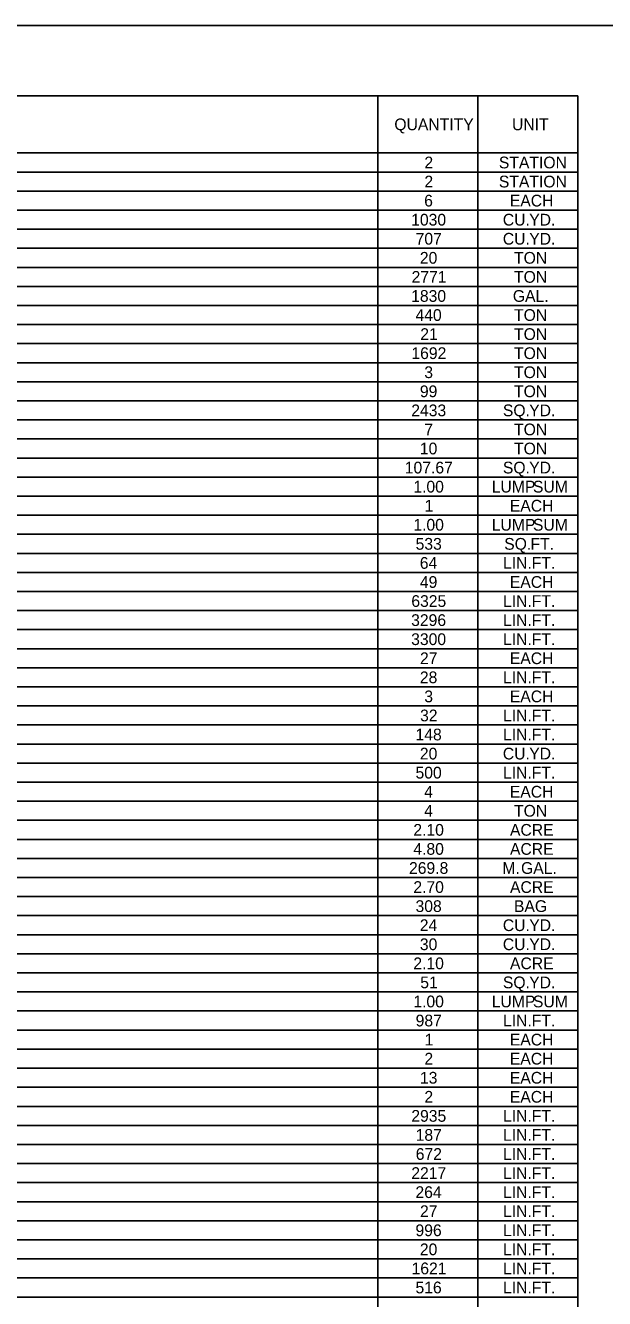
# Model space of a CAD drawing. Extents: x 3289 to 10164, y -1238 to -188.
# Drawn here: x 9306 to 9602, y -839 to -188 of the extents above; entities that cross this region are included whole.
import ezdxf

# ---------------------------------------------------------------- set-up
doc = ezdxf.new("R2010")
doc.units = 0
for name, color, linetype in [('Default', 7, 'Continuous'), ('DSN_DRFT_Named-Boundary', 7, 'Continuous'), ('DSN_QNTY_Annotation', 7, 'Continuous')]:
    doc.layers.add(name, color=color, linetype=linetype)

msp = doc.modelspace()

# ---------------------------------------------------------------- linework, layer by layer
at = {"layer": 'DSN_DRFT_Named-Boundary'}
msp.add_lwpolyline([(8538.57, -1237.74), (10163.57, -1237.74), (10163.57, -187.74), (8538.57, -187.74)], close=True, dxfattribs=at)
at = {"layer": 'DSN_QNTY_Annotation'}
for p, q in [((8900.84, -223.68), (9588.8, -223.68)), ((9486.62, -223.68), (9588.8, -223.68)), ((9486.62, -1023.18), (9486.62, -223.68)), ((9537.71, -1023.18), (9537.71, -223.68)), ((9537.71, -1023.18), (9537.71, -223.68)), ((9588.8, -1023.18), (9588.8, -223.68)), ((8900.84, -252.93), (9588.8, -252.93)), ((9486.62, -837.93), (9486.62, -252.93)), ((8900.84, -262.68), (9588.8, -262.68)), ((8900.84, -272.43), (9588.8, -272.43)), ((8900.84, -282.18), (9588.8, -282.18)), ((8900.84, -291.93), (9588.8, -291.93)), ((8900.84, -301.68), (9588.8, -301.68)), ((8900.84, -311.43), (9588.8, -311.43)), ((8900.84, -321.18), (9588.8, -321.18)), ((8900.84, -330.93), (9588.8, -330.93)), ((8900.84, -340.68), (9588.8, -340.68)), ((8900.84, -350.43), (9588.8, -350.43)), ((8900.84, -360.18), (9588.8, -360.18)), ((8900.84, -369.93), (9588.8, -369.93)), ((8900.84, -379.68), (9588.8, -379.68)), ((8900.84, -389.43), (9588.8, -389.43)), ((8900.84, -399.18), (9588.8, -399.18)), ((8900.84, -408.93), (9588.8, -408.93)), ((8900.84, -418.68), (9588.8, -418.68)), ((8900.84, -428.43), (9588.8, -428.43)), ((8900.84, -438.18), (9588.8, -438.18)), ((8900.84, -447.93), (9588.8, -447.93)), ((8900.84, -457.68), (9588.8, -457.68)), ((8900.84, -467.43), (9588.8, -467.43)), ((8900.84, -477.18), (9588.8, -477.18)), ((8900.84, -486.93), (9588.8, -486.93)), ((8900.84, -496.68), (9588.8, -496.68)), ((8900.84, -506.43), (9588.8, -506.43)), ((8900.84, -516.18), (9588.8, -516.18)), ((8900.84, -525.93), (9588.8, -525.93)), ((8900.84, -535.68), (9588.8, -535.68)), ((8900.84, -545.43), (9588.8, -545.43)), ((8900.84, -555.18), (9588.8, -555.18)), ((8900.84, -564.93), (9588.8, -564.93)), ((8900.84, -574.68), (9588.8, -574.68)), ((8900.84, -584.43), (9588.8, -584.43)), ((8900.84, -594.18), (9588.8, -594.18)), ((8900.84, -603.93), (9588.8, -603.93)), ((8900.84, -613.68), (9588.8, -613.68)), ((8900.84, -623.43), (9588.8, -623.43)), ((8900.84, -633.18), (9588.8, -633.18)), ((8900.84, -642.93), (9588.8, -642.93)), ((8900.84, -652.68), (9588.8, -652.68)), ((8900.84, -662.43), (9588.8, -662.43)), ((8900.84, -672.18), (9588.8, -672.18)), ((8900.84, -681.93), (9588.8, -681.93)), ((8900.84, -691.68), (9588.8, -691.68)), ((8900.84, -701.43), (9588.8, -701.43)), ((8900.84, -711.18), (9588.8, -711.18)), ((8900.84, -720.93), (9588.8, -720.93)), ((8900.84, -730.68), (9588.8, -730.68)), ((8900.84, -740.43), (9588.8, -740.43)), ((8900.84, -750.18), (9588.8, -750.18)), ((8900.84, -759.93), (9588.8, -759.93)), ((8900.84, -769.68), (9588.8, -769.68)), ((8900.84, -779.43), (9588.8, -779.43)), ((8900.84, -789.18), (9588.8, -789.18)), ((8900.84, -798.93), (9588.8, -798.93)), ((8900.84, -808.68), (9588.8, -808.68)), ((8900.84, -818.43), (9588.8, -818.43)), ((8900.84, -828.18), (9588.8, -828.18)), ((8900.84, -837.93), (9588.8, -837.93))]:
    msp.add_line(p, q, dxfattribs=at)

# ---------------------------------------------------------------- texts
at = {"layer": 'Default'}
for s, p in [('QUANTITY', (9495, -241.31)), ('UNIT', (9555.16, -241.31)), ('2', (9510.38, -260.81)), ('STATION', (9548.43, -260.81)), ('2', (9510.38, -270.56)), ('STATION', (9548.43, -270.56)), ('6', (9510.25, -280.31)), ('EACH', (9554.03, -280.31)), ('1030', (9503.6, -290.06)), ('CU.', (9550.45, -290.06)), (' YD.', (9561.73, -290.06)), ('707', (9505.89, -299.81)), ('CU.', (9550.45, -299.81)), (' YD.', (9561.73, -299.81)), ('20', (9508.04, -309.56)), ('TON', (9556.19, -309.56)), ('2771', (9503.81, -319.31)), ('TON', (9556.19, -319.31)), ('1830', (9503.6, -329.06)), ('GAL.', (9555.57, -329.06)), ('440', (9505.82, -338.81)), ('TON', (9556.19, -338.81)), ('21', (9508.25, -348.56)), ('TON', (9556.19, -348.56)), ('1692', (9503.72, -358.31)), ('TON', (9556.19, -358.31)), ('3', (9510.31, -368.06)), ('TON', (9556.19, -368.06)), ('99', (9508.06, -377.81)), ('TON', (9556.19, -377.81)), ('2433', (9503.65, -387.56)), ('SQ.', (9550.48, -387.56)), (' YD.', (9561.7, -387.56)), ('7', (9510.33, -397.31)), ('TON', (9556.19, -397.31)), ('10', (9508.04, -407.06)), ('TON', (9556.19, -407.06)), ('107.67', (9500.34, -416.81)), ('SQ.', (9550.48, -416.81)), (' YD.', (9561.7, -416.81)), ('1.00', (9504.71, -426.56)), ('LUMP', (9544.79, -426.56)), (' SUM', (9563.61, -426.56)), ('1', (9510.47, -436.31)), ('EACH', (9554.03, -436.31)), ('1.00', (9504.71, -446.06)), ('LUMP', (9544.79, -446.06)), (' SUM', (9563.61, -446.06)), ('533', (9505.87, -455.81)), ('SQ.', (9551.16, -455.81)), (' FT.', (9562.38, -455.81)), ('64', (9508.01, -465.56)), ('LIN.', (9550.54, -465.56)), (' FT.', (9563, -465.56)), ('49', (9508.06, -475.31)), ('EACH', (9554.03, -475.31)), ('6325', (9503.68, -485.06)), ('LIN.', (9550.54, -485.06)), (' FT.', (9563, -485.06)), ('3296', (9503.59, -494.81)), ('LIN.', (9550.54, -494.81)), (' FT.', (9563, -494.81)), ('3300', (9503.6, -504.56)), ('LIN.', (9550.54, -504.56)), (' FT.', (9563, -504.56)), ('27', (9508.11, -514.31)), ('EACH', (9554.03, -514.31)), ('28', (9508.05, -524.06)), ('LIN.', (9550.54, -524.06)), (' FT.', (9563, -524.06)), ('3', (9510.31, -533.81)), ('EACH', (9554.03, -533.81)), ('32', (9508.16, -543.56)), ('LIN.', (9550.54, -543.56)), (' FT.', (9563, -543.56)), ('148', (9505.83, -553.31)), ('LIN.', (9550.54, -553.31)), (' FT.', (9563, -553.31)), ('20', (9508.04, -563.06)), ('CU.', (9550.45, -563.06)), (' YD.', (9561.73, -563.06)), ('500', (9505.82, -572.81)), ('LIN.', (9550.54, -572.81)), (' FT.', (9563, -572.81)), ('4', (9510.23, -582.56)), ('EACH', (9554.03, -582.56)), ('4', (9510.23, -592.31)), ('TON', (9556.19, -592.31)), ('2.10', (9504.71, -602.06)), ('ACRE', (9554.11, -602.06)), ('4.80', (9504.71, -611.81)), ('ACRE', (9554.11, -611.81)), ('269.8', (9502.5, -621.56)), ('M.', (9550.21, -621.56)), (' GAL.', (9557.53, -621.56)), ('2.70', (9504.71, -631.31)), ('ACRE', (9554.11, -631.31)), ('308', (9505.83, -641.06)), ('BAG', (9556.14, -641.06)), ('24', (9508.01, -650.81)), ('CU.', (9550.45, -650.81)), (' YD.', (9561.73, -650.81)), ('30', (9508.04, -660.56)), ('CU.', (9550.45, -660.56)), (' YD.', (9561.73, -660.56)), ('2.10', (9504.71, -670.31)), ('ACRE', (9554.11, -670.31)), ('51', (9508.25, -680.06)), ('SQ.', (9550.48, -680.06)), (' YD.', (9561.7, -680.06)), ('1.00', (9504.71, -689.81)), ('LUMP', (9544.79, -689.81)), (' SUM', (9563.61, -689.81)), ('987', (9505.89, -699.56)), ('LIN.', (9550.54, -699.56)), (' FT.', (9563, -699.56)), ('1', (9510.47, -709.31)), ('EACH', (9554.03, -709.31)), ('2', (9510.38, -719.06)), ('EACH', (9554.03, -719.06)), ('13', (9508.09, -728.81)), ('EACH', (9554.03, -728.81)), ('2', (9510.38, -738.56)), ('EACH', (9554.03, -738.56)), ('2935', (9503.68, -748.31)), ('LIN.', (9550.54, -748.31)), (' FT.', (9563, -748.31)), ('187', (9505.89, -758.06)), ('LIN.', (9550.54, -758.06)), (' FT.', (9563, -758.06)), ('672', (9505.94, -767.81)), ('LIN.', (9550.54, -767.81)), (' FT.', (9563, -767.81)), ('2217', (9503.67, -777.56)), ('LIN.', (9550.54, -777.56)), (' FT.', (9563, -777.56)), ('264', (9505.79, -787.31)), ('LIN.', (9550.54, -787.31)), (' FT.', (9563, -787.31)), ('27', (9508.11, -797.06)), ('LIN.', (9550.54, -797.06)), (' FT.', (9563, -797.06)), ('996', (9505.81, -806.81)), ('LIN.', (9550.54, -806.81)), (' FT.', (9563, -806.81)), ('20', (9508.04, -816.56)), ('LIN.', (9550.54, -816.56)), (' FT.', (9563, -816.56)), ('1621', (9503.81, -826.31)), ('LIN.', (9550.54, -826.31)), (' FT.', (9563, -826.31)), ('516', (9505.81, -836.06)), ('LIN.', (9550.54, -836.06)), (' FT.', (9563, -836.06))]:
    msp.add_text(s, height=6, dxfattribs=at).set_placement(p)

doc.saveas('drawing.dxf')
